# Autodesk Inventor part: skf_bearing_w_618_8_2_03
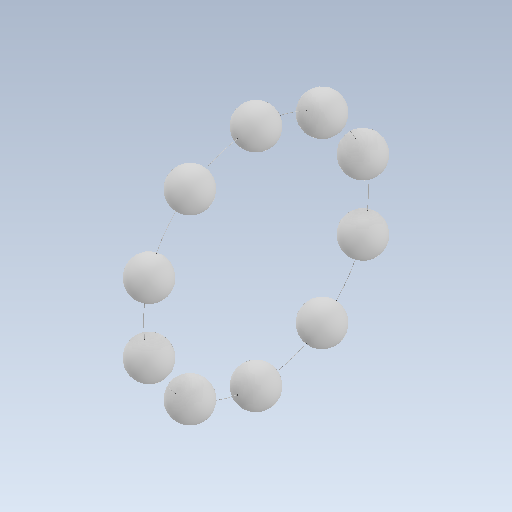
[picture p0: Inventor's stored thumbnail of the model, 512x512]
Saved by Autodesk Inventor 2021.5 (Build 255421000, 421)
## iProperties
Created: 2023-11
Part Number: skf_bearing_w_618_8_2_03
Checked By: TraceParts S.A.
Material: Generic
Catalog Web Link: www.traceparts.com
Document SubType Name: Modeling
Designer: TraceParts
Density: 1 g/cm^3
Appearance: Default
Company: TraceParts S.A.
Author: TraceParts
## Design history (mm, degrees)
feature "skf_bearing_w_618_8_2_03.ipt"
body "Solid1"
